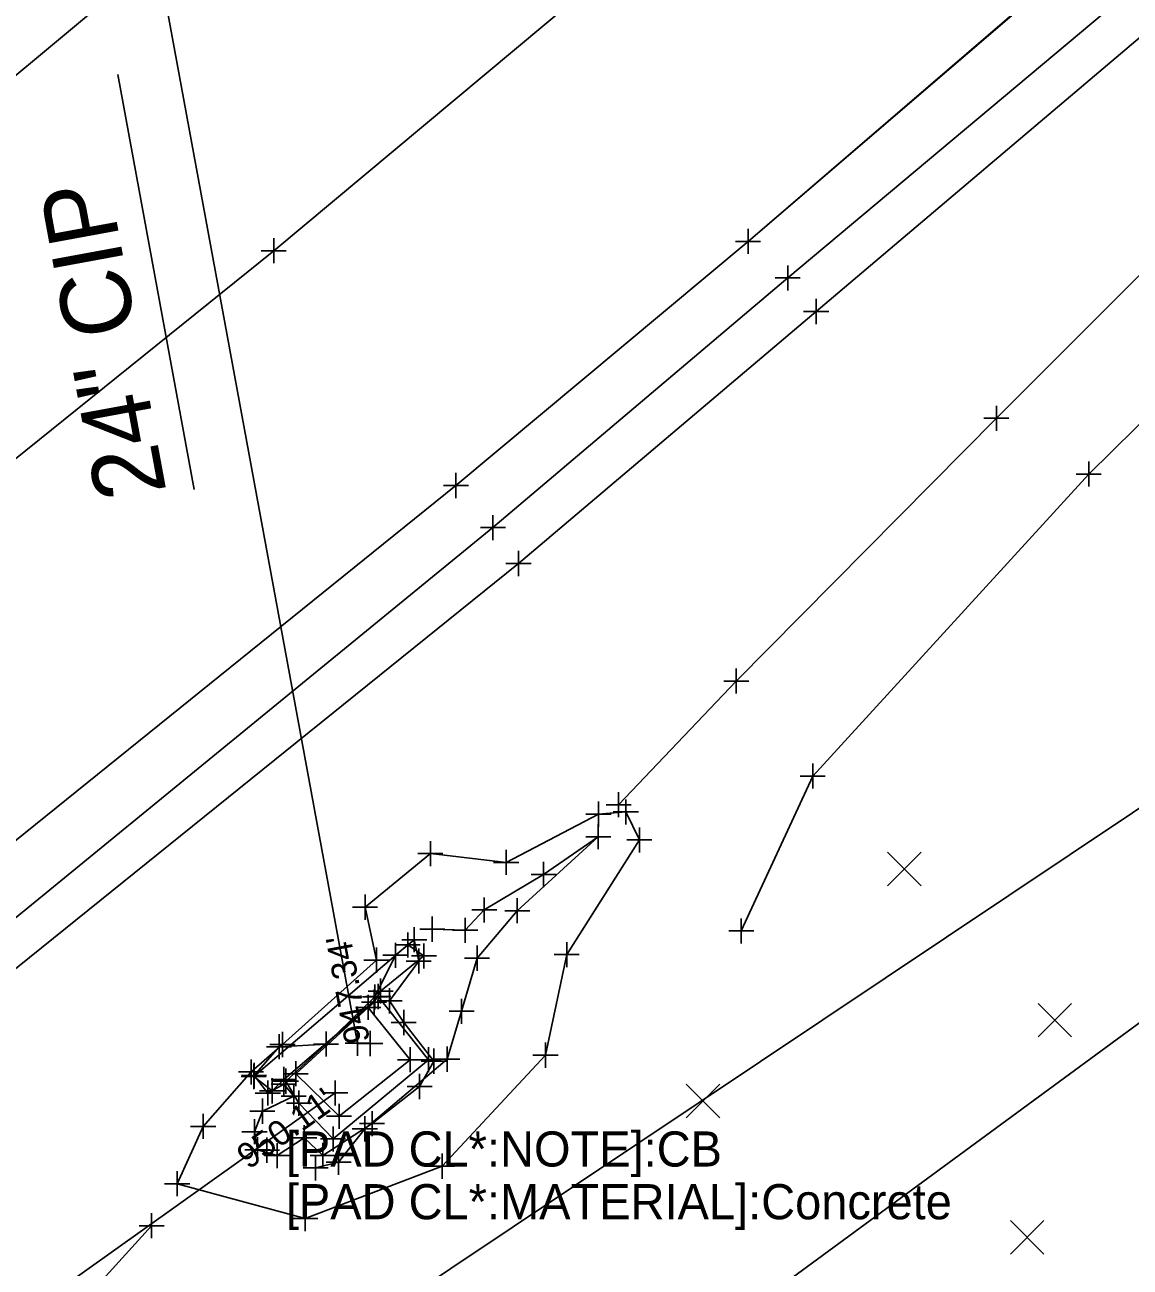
# Model space of a CAD drawing. Extents: x -4 to 139204, y -4 to 477121.
# Drawn here: x 139079.26 to 139123.29, y 476967.42 to 477016.92 of the extents above; entities that cross this region are included whole.
import ezdxf

# ---------------------------------------------------------------- set-up
doc = ezdxf.new("R2010")
doc.units = 0
for name, color, linetype in [('DR_X_Ditch', 7, 'Continuous'), ('DR_X_Headwall', 7, 'Continuous'), ('DR_X_Storm_Sewer', 7, 'Continuous'), ('DR_X_Text', 7, 'Continuous'), ('GE_X_Alignment', 7, 'Continuous'), ('GE_X_Alignment_100_Bearings', 7, 'Continuous'), ('GE_X_Alignment_100_Distances', 7, 'Continuous'), ('PM_X_Edge_Line', 7, 'Continuous'), ('PM_X_Surveyed_Line', 7, 'Continuous'), ('PV_X_COP', 7, 'Continuous'), ('PV_X_EOP', 7, 'Continuous'), ('PV_X_Shoulder', 7, 'Continuous'), ('PV_X_Shoulder_Aggregate', 7, 'Continuous'), ('RD_X_Concrete_Pad', 7, 'Continuous'), ('RD_X_Fence', 7, 'Continuous'), ('SC_Scratch1', 7, 'Continuous'), ('SV_X_Text', 7, 'Continuous'), ('SV_X_Void_Area', 7, 'Continuous'), ('UT_X_Gas', 7, 'Continuous')]:
    doc.layers.add(name, color=color, linetype=linetype)

msp = doc.modelspace()

# ---------------------------------------------------------------- linework, layer by layer
at = {"layer": 'DR_X_Ditch'}
for points in [[(139102.91, 476985.845), (139107.6, 476990.771), (139117.961, 477001.241), (139127.724, 477011.001), (139133.449, 477014.389), (139141.493, 477012.75), (139150.77, 477010.429), (139167.005, 477000.273)], [(139084.31, 476969.071), (139079.627, 476963.915), (139073.397, 476959.844), (139063.705, 476954.01), (139045.774, 476940.83), (139023.925, 476925.276), (139007.837, 476912.933)]]:
    msp.add_lwpolyline(points, dxfattribs=at)
at = {"layer": 'DR_X_Headwall'}
msp.add_lwpolyline([(139088.375, 476975.013), (139089.112, 476974.445), (139089.578, 476974.903), (139093.169, 476977.981), (139093.433, 476978.421), (139095.159, 476979.822), (139094.51, 476980.257)], close=True, dxfattribs=at)
at = {"layer": 'DR_X_Storm_Sewer'}
for p, q in [((139092.516, 476976.342), (139081.899, 477033.935)), ((138907.351, 476843.166), (139091.624, 476974.362)), ((138907.351, 476843.166), (139091.624, 476974.362))]:
    msp.add_line(p, q, dxfattribs=at)
at = {"layer": 'DR_X_Text'}
msp.add_line((139082.96, 477014.942), (139086.01, 476998.399), dxfattribs=at)
at = {"layer": 'GE_X_Alignment'}
for p, q in [((139113.628, 476982.619), (139114.962, 476983.954)), ((139113.628, 476983.954), (139114.962, 476982.619)), ((139119.621, 476976.595), (139120.955, 476977.929)), ((139119.621, 476977.929), (139120.955, 476976.595)), ((139105.608, 476973.372), (139106.942, 476974.706)), ((139105.608, 476974.706), (139106.942, 476973.372)), ((139118.521, 476967.943), (139119.855, 476969.277)), ((139118.521, 476969.277), (139119.855, 476967.943))]:
    msp.add_line(p, q, dxfattribs=at)
at = {"layer": 'GE_X_Alignment_100_Bearings'}
for p, q in [((139108.07, 477008.789), (139108.07, 477007.789)), ((139108.07, 477008.789), (139108.07, 477007.789)), ((139089.175, 477008.416), (139089.175, 477007.416)), ((139089.175, 477008.416), (139089.175, 477007.416)), ((139107.57, 477008.289), (139108.57, 477008.289)), ((139107.57, 477008.289), (139108.57, 477008.289)), ((139108.07, 477008.289), (139108.07, 477008.289)), ((139108.07, 477008.289), (139108.07, 477008.289)), ((139088.675, 477007.916), (139089.675, 477007.916)), ((139088.675, 477007.916), (139089.675, 477007.916)), ((139089.175, 477007.916), (139089.175, 477007.916)), ((139089.175, 477007.916), (139089.175, 477007.916)), ((139109.649, 477007.331), (139109.649, 477006.331)), ((139109.149, 477006.831), (139110.149, 477006.831)), ((139109.649, 477006.831), (139109.649, 477006.831)), ((139110.781, 477005.995), (139110.781, 477004.995)), ((139110.281, 477005.495), (139111.281, 477005.495)), ((139110.781, 477005.495), (139110.781, 477005.495)), ((139117.961, 477001.741), (139117.961, 477000.741)), ((139117.461, 477001.241), (139118.461, 477001.241)), ((139117.961, 477001.241), (139117.961, 477001.241)), ((139121.64, 476999.518), (139121.64, 476998.518)), ((139096.43, 476999.062), (139096.43, 476998.062)), ((139096.43, 476999.062), (139096.43, 476998.062)), ((139121.14, 476999.018), (139122.14, 476999.018)), ((139121.64, 476999.018), (139121.64, 476999.018)), ((139095.93, 476998.562), (139096.93, 476998.562)), ((139095.93, 476998.562), (139096.93, 476998.562)), ((139096.43, 476998.562), (139096.43, 476998.562)), ((139096.43, 476998.562), (139096.43, 476998.562)), ((139097.905, 476997.385), (139097.905, 476996.385)), ((139097.405, 476996.885), (139098.405, 476996.885)), ((139097.905, 476996.885), (139097.905, 476996.885)), ((139098.924, 476995.954), (139098.924, 476994.954)), ((139098.424, 476995.454), (139099.424, 476995.454)), ((139098.924, 476995.454), (139098.924, 476995.454)), ((139107.6, 476991.271), (139107.6, 476990.271)), ((139107.1, 476990.771), (139108.1, 476990.771)), ((139107.6, 476990.771), (139107.6, 476990.771)), ((139110.645, 476987.489), (139110.645, 476986.489)), ((139110.145, 476986.989), (139111.145, 476986.989)), ((139110.645, 476986.989), (139110.645, 476986.989)), ((139102.91, 476986.345), (139102.91, 476985.345)), ((139102.112, 476985.967), (139102.112, 476984.967)), ((139102.41, 476985.845), (139103.41, 476985.845)), ((139102.91, 476985.845), (139102.91, 476985.845)), ((139103.2, 476986.059), (139103.2, 476985.059)), ((139101.612, 476985.467), (139102.612, 476985.467)), ((139102.112, 476985.467), (139102.112, 476985.467)), ((139102.7, 476985.559), (139103.7, 476985.559)), ((139103.2, 476985.559), (139103.2, 476985.559)), ((139102.102, 476985.069), (139102.102, 476984.069)), ((139103.739, 476984.941), (139103.739, 476983.941)), ((139095.415, 476984.396), (139095.415, 476983.396)), ((139101.602, 476984.569), (139102.602, 476984.569)), ((139102.102, 476984.569), (139102.102, 476984.569)), ((139103.239, 476984.441), (139104.239, 476984.441)), ((139103.739, 476984.441), (139103.739, 476984.441)), ((139094.915, 476983.896), (139095.915, 476983.896)), ((139095.415, 476983.896), (139095.415, 476983.896)), ((139098.432, 476984.045), (139098.432, 476983.045)), ((139097.932, 476983.545), (139098.932, 476983.545)), ((139098.432, 476983.545), (139098.432, 476983.545)), ((139099.925, 476983.565), (139099.925, 476982.565)), ((139099.425, 476983.065), (139100.425, 476983.065)), ((139099.925, 476983.065), (139099.925, 476983.065)), ((139092.811, 476982.265), (139092.811, 476981.265)), ((139097.563, 476982.151), (139097.563, 476981.151)), ((139098.876, 476982.12), (139098.876, 476981.12)), ((139092.311, 476981.765), (139093.311, 476981.765)), ((139092.811, 476981.765), (139092.811, 476981.765)), ((139095.489, 476981.387), (139095.489, 476980.387)), ((139096.799, 476981.343), (139096.799, 476980.343)), ((139097.063, 476981.651), (139098.063, 476981.651)), ((139097.563, 476981.651), (139097.563, 476981.651)), ((139098.376, 476981.62), (139099.376, 476981.62)), ((139098.876, 476981.62), (139098.876, 476981.62)), ((139107.799, 476981.317), (139107.799, 476980.317)), ((139094.771, 476980.967), (139094.771, 476979.967)), ((139094.989, 476980.887), (139095.989, 476980.887)), ((139095.489, 476980.887), (139095.489, 476980.887)), ((139096.299, 476980.843), (139097.299, 476980.843)), ((139096.799, 476980.843), (139096.799, 476980.843)), ((139107.299, 476980.817), (139108.299, 476980.817)), ((139107.799, 476980.817), (139107.799, 476980.817)), ((139094.019, 476980.345), (139094.019, 476979.345)), ((139094.271, 476980.467), (139095.271, 476980.467)), ((139094.51, 476980.757), (139094.51, 476979.757)), ((139094.771, 476980.467), (139094.771, 476980.467)), ((139095.159, 476980.322), (139095.159, 476979.322)), ((139100.843, 476980.374), (139100.843, 476979.374)), ((139093.266, 476980.153), (139093.266, 476979.153)), ((139093.519, 476979.845), (139094.519, 476979.845)), ((139094.01, 476980.257), (139095.01, 476980.257)), ((139094.019, 476979.845), (139094.019, 476979.845)), ((139094.51, 476980.257), (139094.51, 476980.257)), ((139094.659, 476979.822), (139095.659, 476979.822)), ((139094.949, 476980.115), (139094.949, 476979.115)), ((139095.159, 476979.822), (139095.159, 476979.822)), ((139097.274, 476980.23), (139097.274, 476979.23)), ((139100.343, 476979.874), (139101.343, 476979.874)), ((139100.843, 476979.874), (139100.843, 476979.874)), ((139092.766, 476979.653), (139093.766, 476979.653)), ((139093.266, 476979.653), (139093.266, 476979.653)), ((139094.449, 476979.615), (139095.449, 476979.615)), ((139094.949, 476979.615), (139094.949, 476979.615)), ((139096.774, 476979.73), (139097.774, 476979.73)), ((139097.274, 476979.73), (139097.274, 476979.73)), ((139093.433, 476978.921), (139093.433, 476977.921)), ((139092.933, 476978.421), (139093.933, 476978.421)), ((139093.169, 476978.481), (139093.169, 476977.481)), ((139093.204, 476978.687), (139093.204, 476977.687)), ((139093.34, 476978.706), (139093.34, 476977.706)), ((139093.433, 476978.421), (139093.433, 476978.421)), ((139093.788, 476978.533), (139093.788, 476977.533)), ((139092.669, 476977.981), (139093.669, 476977.981)), ((139092.704, 476978.187), (139093.704, 476978.187)), ((139092.84, 476978.206), (139093.84, 476978.206)), ((139092.941, 476978.271), (139092.941, 476977.271)), ((139093.169, 476977.981), (139093.169, 476977.981)), ((139093.204, 476978.187), (139093.204, 476978.187)), ((139093.288, 476978.033), (139094.288, 476978.033)), ((139093.34, 476978.206), (139093.34, 476978.206)), ((139093.788, 476978.033), (139093.788, 476978.033)), ((139096.658, 476978.116), (139096.658, 476977.116)), ((139092.441, 476977.771), (139093.441, 476977.771)), ((139092.941, 476977.771), (139092.941, 476977.771)), ((139094.351, 476977.67), (139094.351, 476976.67)), ((139096.158, 476977.616), (139097.158, 476977.616)), ((139096.658, 476977.616), (139096.658, 476977.616)), ((139093.851, 476977.17), (139094.851, 476977.17)), ((139094.351, 476977.17), (139094.351, 476977.17)), ((139089.387, 476976.704), (139089.387, 476975.704)), ((139089.522, 476976.79), (139089.522, 476975.79)), ((139091.257, 476976.81), (139091.257, 476975.81)), ((139099.999, 476976.366), (139099.999, 476975.366)), ((139088.887, 476976.204), (139089.887, 476976.204)), ((139089.022, 476976.29), (139090.022, 476976.29)), ((139089.387, 476976.204), (139089.387, 476976.204)), ((139089.522, 476976.29), (139089.522, 476976.29)), ((139090.757, 476976.31), (139091.757, 476976.31)), ((139091.257, 476976.31), (139091.257, 476976.31)), ((139094.603, 476976.186), (139094.603, 476975.186)), ((139095.342, 476976.185), (139095.342, 476975.185)), ((139095.553, 476976.126), (139095.553, 476975.126)), ((139096.086, 476976.207), (139096.086, 476975.207)), ((139099.499, 476975.866), (139100.499, 476975.866)), ((139099.999, 476975.866), (139099.999, 476975.866)), ((139088.27, 476975.698), (139088.27, 476974.698)), ((139088.375, 476975.513), (139088.375, 476974.513)), ((139088.389, 476975.558), (139088.389, 476974.558)), ((139089.578, 476975.403), (139089.578, 476974.403)), ((139090.05, 476975.627), (139090.05, 476974.627)), ((139094.103, 476975.686), (139095.103, 476975.686)), ((139094.603, 476975.686), (139094.603, 476975.686)), ((139094.842, 476975.685), (139095.842, 476975.685)), ((139095.053, 476975.626), (139096.053, 476975.626)), ((139095.342, 476975.685), (139095.342, 476975.685)), ((139095.553, 476975.626), (139095.553, 476975.626)), ((139095.586, 476975.707), (139096.586, 476975.707)), ((139096.086, 476975.707), (139096.086, 476975.707)), ((139087.77, 476975.198), (139088.77, 476975.198)), ((139087.875, 476975.013), (139088.875, 476975.013)), ((139087.889, 476975.058), (139088.889, 476975.058)), ((139088.27, 476975.198), (139088.27, 476975.198)), ((139088.375, 476975.013), (139088.375, 476975.013)), ((139088.389, 476975.058), (139088.389, 476975.058)), ((139089.078, 476974.903), (139090.078, 476974.903)), ((139089.112, 476974.945), (139089.112, 476973.945)), ((139089.55, 476975.127), (139090.55, 476975.127)), ((139089.572, 476975.215), (139089.572, 476974.215)), ((139089.578, 476974.903), (139089.578, 476974.903)), ((139089.657, 476975.329), (139089.657, 476974.329)), ((139090.05, 476975.127), (139090.05, 476975.127)), ((139094.987, 476975.117), (139094.987, 476974.117)), ((139088.612, 476974.445), (139089.612, 476974.445)), ((139088.94, 476974.858), (139088.94, 476973.858)), ((139089.072, 476974.715), (139090.072, 476974.715)), ((139089.112, 476974.445), (139089.112, 476974.445)), ((139089.157, 476974.829), (139090.157, 476974.829)), ((139089.572, 476974.715), (139089.572, 476974.715)), ((139089.657, 476974.829), (139089.657, 476974.829)), ((139089.968, 476974.732), (139089.968, 476973.732)), ((139090.18, 476974.453), (139090.18, 476973.453)), ((139094.487, 476974.617), (139095.487, 476974.617)), ((139094.987, 476974.617), (139094.987, 476974.617)), ((139088.44, 476974.358), (139089.44, 476974.358)), ((139088.722, 476974.137), (139088.722, 476973.137)), ((139088.94, 476974.358), (139088.94, 476974.358)), ((139089.468, 476974.232), (139090.468, 476974.232)), ((139089.68, 476973.953), (139090.68, 476973.953)), ((139089.968, 476974.232), (139089.968, 476974.232)), ((139090.18, 476973.953), (139090.18, 476973.953)), ((139091.775, 476973.93), (139091.775, 476972.93)), ((139086.364, 476973.53), (139086.364, 476972.53)), ((139088.222, 476973.637), (139089.222, 476973.637)), ((139088.722, 476973.637), (139088.722, 476973.637)), ((139091.275, 476973.43), (139092.275, 476973.43)), ((139091.775, 476973.43), (139091.775, 476973.43)), ((139092.802, 476973.43), (139092.802, 476972.43)), ((139093.089, 476973.64), (139093.089, 476972.64)), ((139085.864, 476973.03), (139086.864, 476973.03)), ((139086.364, 476973.03), (139086.364, 476973.03)), ((139088.408, 476973.316), (139088.408, 476972.316)), ((139090.387, 476973.079), (139090.387, 476972.079)), ((139091.535, 476973.028), (139091.535, 476972.028)), ((139092.302, 476972.93), (139093.302, 476972.93)), ((139092.589, 476973.14), (139093.589, 476973.14)), ((139092.802, 476972.93), (139092.802, 476972.93)), ((139093.089, 476973.14), (139093.089, 476973.14)), ((139087.908, 476972.816), (139088.908, 476972.816)), ((139088.408, 476972.816), (139088.408, 476972.816)), ((139088.528, 476972.594), (139088.528, 476971.594)), ((139089.887, 476972.579), (139090.887, 476972.579)), ((139090.387, 476972.579), (139090.387, 476972.579)), ((139091.035, 476972.528), (139092.035, 476972.528)), ((139091.535, 476972.528), (139091.535, 476972.528)), ((139088.028, 476972.094), (139089.028, 476972.094)), ((139088.528, 476972.094), (139088.528, 476972.094)), ((139089.31, 476972.367), (139089.31, 476971.367)), ((139091.13, 476972.375), (139091.13, 476971.375)), ((139091.759, 476972.102), (139091.759, 476971.102)), ((139095.877, 476971.944), (139095.877, 476970.944)), ((139088.81, 476971.867), (139089.81, 476971.867)), ((139089.31, 476971.867), (139089.31, 476971.867)), ((139090.63, 476971.875), (139091.63, 476971.875)), ((139090.843, 476971.875), (139090.843, 476970.875)), ((139091.13, 476971.875), (139091.13, 476971.875)), ((139091.259, 476971.602), (139092.259, 476971.602)), ((139091.759, 476971.602), (139091.759, 476971.602)), ((139095.377, 476971.444), (139096.377, 476971.444)), ((139095.877, 476971.444), (139095.877, 476971.444)), ((139085.329, 476971.247), (139085.329, 476970.247)), ((139090.343, 476971.375), (139091.343, 476971.375)), ((139090.843, 476971.375), (139090.843, 476971.375)), ((139084.829, 476970.747), (139085.829, 476970.747)), ((139085.329, 476970.747), (139085.329, 476970.747)), ((139084.31, 476969.571), (139084.31, 476968.571)), ((139090.428, 476969.855), (139090.428, 476968.855)), ((139083.81, 476969.071), (139084.81, 476969.071)), ((139084.31, 476969.071), (139084.31, 476969.071)), ((139089.928, 476969.355), (139090.928, 476969.355)), ((139090.428, 476969.355), (139090.428, 476969.355))]:
    msp.add_line(p, q, dxfattribs=at)
at = {"layer": 'GE_X_Alignment_100_Distances'}
for p, q in [((139092.516, 476976.842), (139092.516, 476975.842)), ((139093.015, 476976.832), (139093.015, 476975.832)), ((139092.016, 476976.342), (139093.016, 476976.342)), ((139092.515, 476976.332), (139093.515, 476976.332)), ((139092.516, 476976.342), (139092.516, 476976.342)), ((139093.015, 476976.332), (139093.015, 476976.332)), ((139091.624, 476974.862), (139091.624, 476973.862)), ((139091.124, 476974.362), (139092.124, 476974.362)), ((139091.624, 476974.362), (139091.624, 476974.362)), ((139088.902, 476972.582), (139088.902, 476971.582)), ((139088.402, 476972.082), (139089.402, 476972.082)), ((139088.902, 476972.082), (139088.902, 476972.082))]:
    msp.add_line(p, q, dxfattribs=at)
at = {"layer": 'PM_X_Edge_Line'}
for points in [[(138923.242, 476898.186), (138964.692, 476927.855), (139004.314, 476956.805), (139026.754, 476973.572), (139043.226, 476986.096), (139066.294, 477004.413), (139084.97, 477019.976), (139103.96, 477036.155), (139120.378, 477050.406), (139142.062, 477069.904), (139165.575, 477091.057)], [(139119.978, 477018.535), (139108.07, 477008.289), (139096.43, 476998.562), (139075.62, 476981.789), (139057.894, 476968.012), (139018.116, 476938.023), (138977.717, 476908.355), (138952.937, 476890.592), (138936.689, 476878.892)]]:
    msp.add_lwpolyline(points, dxfattribs=at)
at = {"layer": 'PM_X_Surveyed_Line'}
msp.add_lwpolyline([(138930.184, 476888.564), (138972.007, 476918.562), (139012.493, 476948.198), (139029.811, 476961.233), (139052.078, 476978.039), (139073.558, 476995.35), (139089.175, 477007.916), (139110.846, 477026.03), (139111.346, 477026.745)], dxfattribs=at)
at = {"layer": 'PV_X_COP'}
msp.add_lwpolyline([(138930.195, 476888.554), (138972.007, 476918.562), (139012.493, 476948.198), (139029.811, 476961.233), (139052.078, 476978.039), (139073.558, 476995.35), (139089.175, 477007.916), (139110.846, 477026.03), (139129.377, 477042.526), (139155.719, 477066.268), (139171.584, 477080.905)], dxfattribs=at)
at = {"layer": 'PV_X_EOP'}
for points in [[(138923.266, 476898.028), (138964.692, 476927.855), (139004.314, 476956.805), (139026.754, 476973.572), (139043.226, 476986.096), (139066.294, 477004.413), (139084.97, 477019.976), (139103.96, 477036.155), (139120.378, 477050.406), (139142.062, 477069.904), (139165.559, 477091.096)], [(139119.987, 477018.511), (139108.07, 477008.289), (139096.43, 476998.562), (139075.62, 476981.789), (139057.894, 476968.012), (139018.116, 476938.023), (138977.717, 476908.355), (138952.937, 476890.592), (138936.542, 476879.008)]]:
    msp.add_lwpolyline(points, dxfattribs=at)
at = {"layer": 'PV_X_Shoulder'}
msp.add_lwpolyline([(139183.638, 477072.424), (139153.919, 477045.299), (139136.787, 477030.023), (139126.343, 477020.832), (139109.649, 477006.831), (139097.905, 476996.885), (139077.102, 476979.89), (139059.387, 476965.891), (139020.106, 476935.561), (139003.351, 476922.965), (138997.924, 476918.666), (138993.965, 476914.098), (138990.512, 476910.309), (138981.306, 476903.856), (138956.564, 476885.614), (138940.343, 476873.773)], dxfattribs=at)
at = {"layer": 'PV_X_Shoulder_Aggregate'}
msp.add_lwpolyline([(139124.206, 477016.86), (139110.781, 477005.495), (139098.924, 476995.454), (139078.061, 476978.654), (139060.667, 476964.123), (139021.044, 476934.127), (139004.817, 476921.429), (138999.267, 476916.949), (138995.343, 476912.815), (138991.494, 476909.144)], dxfattribs=at)
at = {"layer": 'RD_X_Concrete_Pad'}
for points in [[(139093.34, 476978.206), (139095.342, 476975.685), (139091.535, 476972.528), (139090.18, 476973.953), (139089.657, 476974.829)], [(139090.05, 476975.127), (139091.775, 476973.43), (139094.603, 476975.686), (139092.941, 476977.771)]]:
    msp.add_lwpolyline(points, close=True, dxfattribs=at)
at = {"layer": 'RD_X_Fence'}
msp.add_lwpolyline([(139170.211, 476966.83), (139152.176, 476981.457), (139140.024, 476988.541), (139126.511, 476979.248), (139077.418, 476943.213), (139054.3, 476926.021), (139036.036, 476912.286), (139009.14, 476892.322), (138983.005, 476872.624), (138984.167, 476847.153), (138984.924, 476831.748)], dxfattribs=at)
at = {"layer": 'SC_Scratch1'}
for points in [[(139107.799, 476980.817), (139110.645, 476986.989), (139121.64, 476999.018), (139130.051, 477007.3), (139135.673, 477009.934), (139140.914, 477008.455), (139151.523, 477005.671), (139162.013, 476994.538)], [(139095.489, 476980.887), (139096.799, 476980.843), (139097.563, 476981.651), (139099.925, 476983.065), (139102.102, 476984.569), (139098.876, 476981.62), (139097.274, 476979.73), (139096.658, 476977.616), (139096.086, 476975.707), (139092.802, 476972.93), (139091.759, 476971.602), (139090.843, 476971.375)]]:
    msp.add_lwpolyline(points, dxfattribs=at)
msp.add_lwpolyline([(139085.329, 476970.747), (139090.428, 476969.355), (139095.877, 476971.444), (139099.999, 476975.866), (139100.843, 476979.874), (139103.739, 476984.441), (139103.2, 476985.559), (139102.112, 476985.467), (139098.432, 476983.545), (139095.415, 476983.896), (139092.811, 476981.765), (139093.266, 476979.653), (139089.522, 476976.29), (139088.27, 476975.198), (139086.364, 476973.03)], close=True, dxfattribs=at)
at = {"layer": 'SV_X_Void_Area'}
msp.add_lwpolyline([(139088.389, 476975.058), (139088.94, 476974.358), (139089.572, 476974.715), (139089.968, 476974.232), (139088.722, 476973.637), (139088.408, 476972.816), (139088.528, 476972.094), (139089.31, 476971.867), (139090.387, 476972.579), (139091.13, 476971.875), (139093.089, 476973.14), (139094.987, 476974.617), (139095.553, 476975.626), (139094.351, 476977.17), (139093.788, 476978.033), (139094.949, 476979.615), (139094.771, 476980.467), (139094.019, 476979.845), (139093.204, 476978.187), (139091.257, 476976.31), (139089.387, 476976.204)], close=True, dxfattribs=at)
at = {"layer": 'UT_X_Gas'}
msp.add_lwpolyline([(139004.075, 476900.734), (139028.392, 476919.279), (139049.353, 476936.04), (139135.72, 476993.765), (139150.82, 477005.632), (139162.46, 477015.27), (139171.782, 477023.038), (139186.18, 477034.164), (139199.281, 477045.473), (139201.496, 477047.37), (139194.822, 477055.784), (139186.687, 477066.39), (139182.688, 477071.332), (139173.257, 477082.641), (139163.808, 477093.452), (139160.449, 477097.743)], dxfattribs=at)

# ---------------------------------------------------------------- texts
at = {"layer": 'DR_X_Text'}
msp.add_text('24" CIP', height=2.8, rotation=100.4449, dxfattribs=at).set_placement((139084.905, 476998.311))
at = {"layer": 'SC_Scratch1'}
for s, rotation, p in [("947.34'", 100.4449, (139093.008, 476976.433)), ("950.11'", 35.4496, (139088.168, 476971.288)), ("950.11'", 35.4496, (139088.168, 476971.288))]:
    msp.add_text(s, height=1, rotation=rotation, dxfattribs=at).set_placement(p)
at = {"layer": 'SV_X_Text'}
for s, p in [('[PAD CL*:NOTE]:CB', (139089.657, 476971.429)), ('[PAD CL*:MATERIAL]:Concrete', (139089.657, 476969.329))]:
    msp.add_text(s, height=1.4, dxfattribs=at).set_placement(p)

doc.saveas('drawing.dxf')
